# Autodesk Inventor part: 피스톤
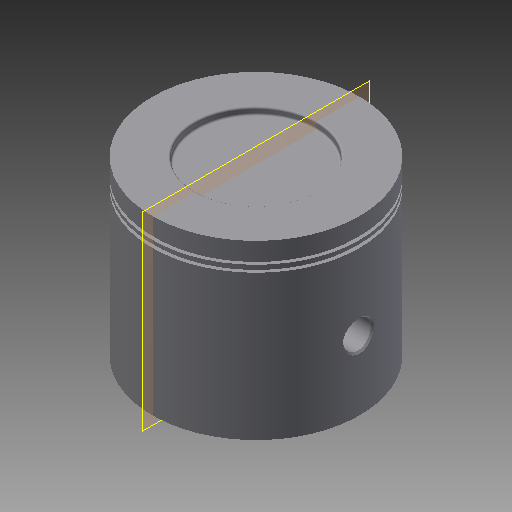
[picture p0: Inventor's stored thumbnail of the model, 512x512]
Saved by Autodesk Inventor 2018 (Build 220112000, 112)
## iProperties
Created: 2016-11
Part Number: 피스톤
Material: 강철, 탄소
Document SubType Name: Modeling
Designer: mduedu
Density: 7.87 g/cm^3
Mass: 410.154 g
Surface Area: 237.492 cm^2
Volume: 52.1161 cm^3
Appearance: 기본값
Author: mduedu
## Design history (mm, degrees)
sketch "스케치1"
  geometry: C1 r 30 at (0, 0); 1 further point
  constraints: 1 centre point, 1 coincident
  dimensions: "d0" = 60 diameter of C1
extrude "돌출1" new body sketch "스케치1" distance "d1" = 50; taper "d2" = 0 deg
sketch "스케치2"
  geometry: C1 r 28 at (0, 0); 1 further point
  constraints: 1 centre point, 1 coincident
  dimensions: "d3" = 56 diameter of C1
extrude "돌출2" cut sketch "스케치2" distance "d4" = 45; taper "d5" = 0 deg
sketch "스케치3"
  geometry: L1 (30, 0)-(30, 50) reference; L2 (30, 45)-(29, 45); L3 (29, 45)-(29, 44); L4 (29, 44)-(30, 44); L5 (30, 44)-(30, 45); L6 (30, 43)-(29, 43); L7 (29, 43)-(29, 42); L8 (29, 42)-(30, 42); L9 (30, 42)-(30, 43); L10 (30, 50)-(-30, 50) reference; L11 (0, 50)-(0, 0)
  constraints: 18 end point, 4 parallel, 3 equal length, 3 perpendicular, 2 horizontal, 2 point on line, 1 midpoint
  dimensions: "d6" = 1 distance of L2.start L2.end; "d8" = 5 distance between parallel lines of L10 L2; "d9" = 1 distance between parallel lines of L6 L4
revolve "회전1" sketch "스케치3" stored, may be unused: angle "d10" = 90 deg
node "작업 평면1"
sketch "스케치4"
  geometry: L1 (0, -22.978)-(45, -22.978) reference; L2 (45, -22.978)-(45, 22.978) reference; L3 (45, 22.978)-(0, 22.978) reference; L4 (0, 22.978)-(0, 25.377) reference; L5 (0, 25.377)-(42, 25.377) reference; L6 (42, 25.377)-(42, 24.187) reference; L7 (42, 24.187)-(43, 24.187) reference; L8 (43, 24.187)-(43, 25.377) reference; L9 (43, 25.377)-(44, 25.377) reference; L10 (44, 25.377)-(44, 24.187) reference; L11 (44, 24.187)-(45, 24.187) reference; L12 (45, 24.187)-(45, 25.377) reference; L13 (45, 25.377)-(50, 25.377) reference; L14 (50, 25.377)-(50, -25.377) reference; L15 (50, -25.377)-(45, -25.377) reference; L16 (45, -25.377)-(45, -24.187) reference; L17 (45, -24.187)-(44, -24.187) reference; L18 (44, -24.187)-(44, -25.377) reference; L19 (44, -25.377)-(43, -25.377) reference; L20 (43, -25.377)-(43, -24.187) reference; L21 (43, -24.187)-(42, -24.187) reference; L22 (42, -24.187)-(42, -25.377) reference; L23 (42, -25.377)-(0, -25.377) reference; L24 (0, -25.377)-(0, -22.978) reference; L25 (12.5, 22.978)-(45, 22.978); L26 (45, 22.978)-(45, -22.978); L27 (45, -22.978)-(12.5, -22.978); L28 (12.5, -22.978)-(12.5, 22.978); C1 r 7.5 at (20, 0); C2 r 4 at (20, 0); 1 further point
  constraints: 8 end point, 2 centre point, 2 parallel, 1 coincident, 1 horizontal, 1 horizontal alignment, 1 perpendicular, 1 point on line, 1 tangent
  dimensions: "d12" = 15 diameter of C1; "d13" = 8 diameter of C2; "d14" = 20 distance of point (0, 0) C1.centre
  node "절단 모서리 투영1"
extrude "돌출3" join sketch "스케치4" stored distance "d15" = 11.75; taper "d16" = 0 deg
extrude "돌출4" cut sketch "스케치4" extent not by distance; stored distance "d17" = 72; taper "d18" = 0 deg
fillet "모깎기2" dims "d20" = 3
chamfer "모따기1" distance "d21" = 0.5; stored, may be unused: second distance "d22" = 2, angle "d23" = 45 deg
chamfer "모따기2" distance "d24" = 0.5; stored, may be unused: second distance "d25" = 2, angle "d26" = 45 deg
sketch "스케치5"
  geometry: C1 r 17.5 at (0, 0); 1 further point
  constraints: 1 centre point, 1 coincident
  dimensions: "d27" = 35 diameter of C1
extrude "돌출5" cut sketch "스케치5" distance "d28" = 2; taper "d29" = 0 deg
fillet "모깎기3" dims "d30" = 0.5
node "솔리드1"
mirror "대칭1"
other parameters: "d11" = -16
